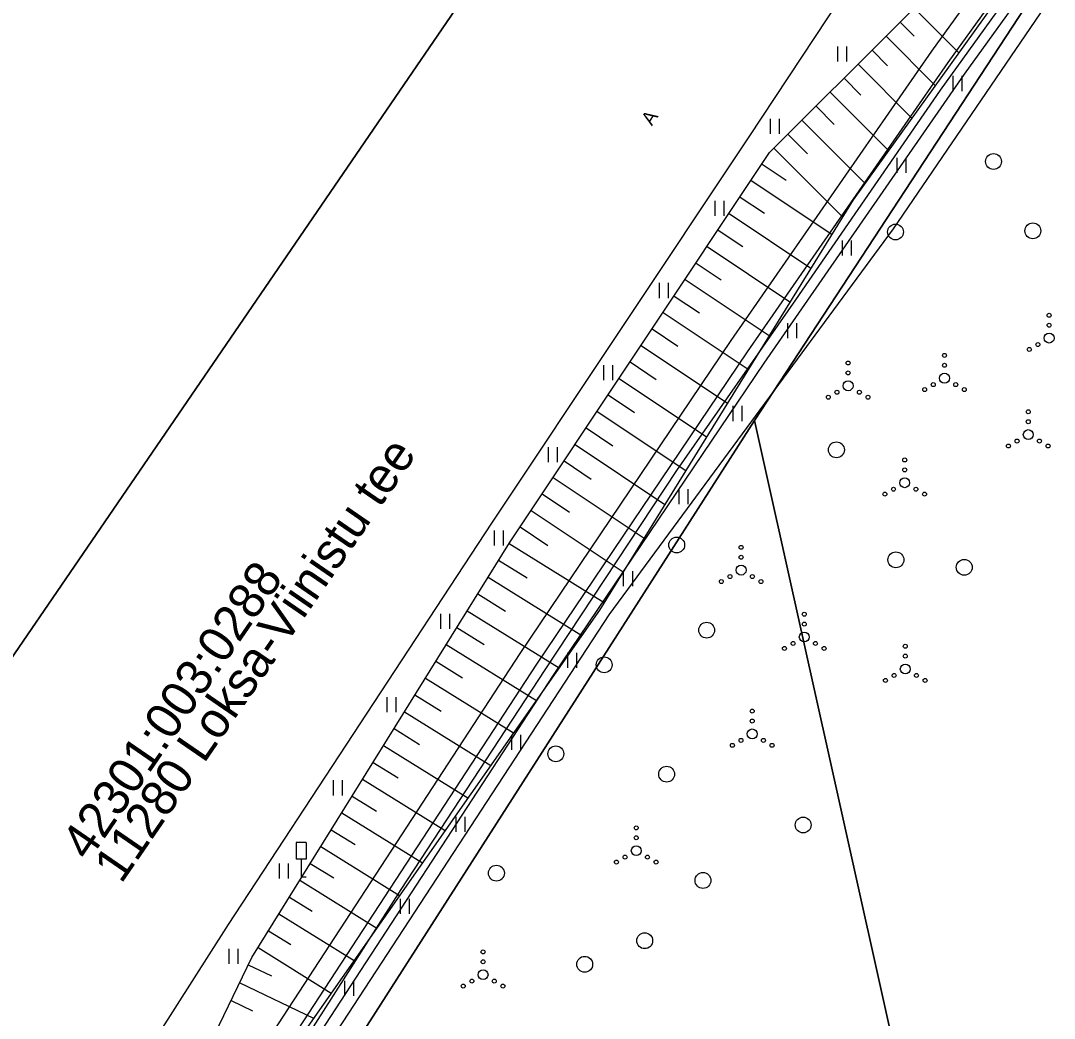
# Model space of a CAD drawing. Extents: x 599446 to 599962, y 6608194 to 6608886.
# Drawn here: x 599780.3 to 599832.4, y 6608609.2 to 6608659.5 of the extents above; entities that cross this region are included whole.
import ezdxf

# ---------------------------------------------------------------- set-up
doc = ezdxf.new("R2010")
doc.units = 0
for name, color, linetype in [('HALJASTUS', 7, 'Continuous'), ('KASUTUSALA', 7, 'Continuous'), ('LIIKLUS', 7, 'Continuous'), ('MPKAABEL', 7, 'Continuous'), ('PIIR', 7, 'Continuous'), ('PR_SIDE', 7, 'Continuous'), ('RELJEEF', 7, 'Continuous'), ('TEE', 7, 'Continuous')]:
    doc.layers.add(name, color=color, linetype=linetype)

msp = doc.modelspace()

# ---------------------------------------------------------------- linework, layer by layer
at = {"layer": 'HALJASTUS'}
for p, q in [((599821.508, 6608658.179), (599821.508, 6608657.418)), ((599821.963, 6608658.179), (599821.963, 6608657.418)), ((599827.314, 6608656.694), (599827.314, 6608655.933)), ((599827.769, 6608656.694), (599827.769, 6608655.933)), ((599818.112, 6608654.531), (599818.112, 6608653.77)), ((599818.567, 6608654.531), (599818.567, 6608653.77)), ((599824.489, 6608652.57), (599824.489, 6608651.808)), ((599824.944, 6608652.57), (599824.944, 6608651.808)), ((599815.31, 6608650.39), (599815.31, 6608649.629)), ((599815.765, 6608650.39), (599815.765, 6608649.629)), ((599821.732, 6608648.398), (599821.732, 6608647.637)), ((599822.187, 6608648.398), (599822.187, 6608647.637)), ((599812.509, 6608646.248), (599812.509, 6608645.487)), ((599812.964, 6608646.248), (599812.964, 6608645.487)), ((599818.975, 6608644.227), (599818.975, 6608643.466)), ((599819.43, 6608644.227), (599819.43, 6608643.466)), ((599809.707, 6608642.107), (599809.707, 6608641.346)), ((599810.162, 6608642.107), (599810.162, 6608641.346)), ((599816.231, 6608640.047), (599816.231, 6608639.286)), ((599816.686, 6608640.047), (599816.686, 6608639.286)), ((599806.906, 6608637.965), (599806.906, 6608637.204)), ((599807.361, 6608637.965), (599807.361, 6608637.204)), ((599813.506, 6608635.855), (599813.506, 6608635.094)), ((599813.962, 6608635.855), (599813.962, 6608635.094)), ((599804.193, 6608633.765), (599804.193, 6608633.004)), ((599804.648, 6608633.765), (599804.648, 6608633.004)), ((599810.701, 6608631.717), (599810.701, 6608630.956)), ((599811.156, 6608631.717), (599811.156, 6608630.956)), ((599801.482, 6608629.564), (599801.482, 6608628.803)), ((599801.937, 6608629.564), (599801.937, 6608628.803)), ((599807.88, 6608627.588), (599807.88, 6608626.827)), ((599808.336, 6608627.588), (599808.336, 6608626.827)), ((599798.771, 6608625.363), (599798.771, 6608624.602)), ((599799.226, 6608625.363), (599799.226, 6608624.602)), ((599805.064, 6608623.457), (599805.064, 6608622.696)), ((599805.519, 6608623.457), (599805.519, 6608622.696)), ((599796.06, 6608621.161), (599796.06, 6608620.4)), ((599796.515, 6608621.161), (599796.515, 6608620.4)), ((599802.254, 6608619.321), (599802.254, 6608618.56)), ((599802.709, 6608619.321), (599802.709, 6608618.56)), ((599793.349, 6608616.96), (599793.349, 6608616.199)), ((599793.804, 6608616.96), (599793.804, 6608616.199)), ((599799.444, 6608615.185), (599799.444, 6608614.424)), ((599799.899, 6608615.185), (599799.899, 6608614.424)), ((599790.805, 6608612.661), (599790.805, 6608611.899)), ((599791.26, 6608612.661), (599791.26, 6608611.899)), ((599796.634, 6608611.049), (599796.634, 6608610.288)), ((599797.089, 6608611.049), (599797.089, 6608610.288))]:
    msp.add_line(p, q, dxfattribs=at)
msp.add_lwpolyline([(599854.437, 6608582.858), (599845.632, 6608584.378), (599826.804, 6608588.268), (599809.044, 6608591.586), (599807.451, 6608590.502), (599796.451, 6608594.999), (599793.207, 6608594.269), (599791.661, 6608599.006), (599795.433, 6608607.227), (599809.992, 6608629.503), (599824.333, 6608648.974), (599834.941, 6608664.558), (599840.035, 6608665.745), (599843.227, 6608674.906), (599844.956, 6608681.949), (599852.543, 6608691.108)], dxfattribs=at)
for centre, radius in [((599829.374, 6608652.379), 0.4), ((599824.427, 6608648.821), 0.4), ((599831.357, 6608648.88), 0.4), ((599832.177, 6608644.619), 0.1), ((599832.177, 6608644.119), 0.1), ((599832.177, 6608643.469), 0.25), ((599831.612, 6608643.144), 0.1), ((599826.9, 6608642.596), 0.1), ((599831.177, 6608642.894), 0.1), ((599822.041, 6608642.212), 0.1), ((599826.9, 6608642.096), 0.1), ((599822.041, 6608641.712), 0.1), ((599826.9, 6608641.446), 0.25), ((599822.041, 6608641.062), 0.25), ((599825.9, 6608640.871), 0.1), ((599826.335, 6608641.121), 0.1), ((599827.465, 6608641.121), 0.1), ((599827.9, 6608640.871), 0.1), ((599821.041, 6608640.487), 0.1), ((599821.476, 6608640.737), 0.1), ((599822.606, 6608640.737), 0.1), ((599823.041, 6608640.487), 0.1), ((599831.125, 6608639.75), 0.1), ((599831.125, 6608639.25), 0.1), ((599830.56, 6608638.275), 0.1), ((599831.125, 6608638.6), 0.25), ((599831.69, 6608638.275), 0.1), ((599821.449, 6608637.832), 0.4), ((599830.125, 6608638.025), 0.1), ((599832.125, 6608638.025), 0.1), ((599824.893, 6608637.321), 0.1), ((599824.893, 6608636.821), 0.1), ((599824.893, 6608636.171), 0.25), ((599824.328, 6608635.846), 0.1), ((599825.458, 6608635.846), 0.1), ((599823.893, 6608635.596), 0.1), ((599825.893, 6608635.596), 0.1), ((599813.394, 6608633.032), 0.4), ((599816.644, 6608632.914), 0.1), ((599824.449, 6608632.286), 0.4), ((599816.644, 6608632.414), 0.1), ((599827.896, 6608631.905), 0.4), ((599816.644, 6608631.764), 0.25), ((599815.644, 6608631.189), 0.1), ((599816.079, 6608631.439), 0.1), ((599817.209, 6608631.439), 0.1), ((599817.644, 6608631.189), 0.1), ((599819.828, 6608629.539), 0.1), ((599814.905, 6608628.732), 0.4), ((599819.828, 6608629.039), 0.1), ((599819.828, 6608628.389), 0.25), ((599819.263, 6608628.064), 0.1), ((599820.393, 6608628.064), 0.1), ((599824.922, 6608627.924), 0.1), ((599818.828, 6608627.814), 0.1), ((599820.828, 6608627.814), 0.1), ((599824.922, 6608627.424), 0.1), ((599809.736, 6608626.986), 0.4), ((599824.922, 6608626.774), 0.25), ((599824.357, 6608626.449), 0.1), ((599825.487, 6608626.449), 0.1), ((599823.922, 6608626.199), 0.1), ((599825.922, 6608626.199), 0.1), ((599817.202, 6608624.65), 0.1), ((599817.202, 6608624.15), 0.1), ((599816.637, 6608623.175), 0.1), ((599817.202, 6608623.5), 0.25), ((599817.767, 6608623.175), 0.1), ((599807.297, 6608622.498), 0.4), ((599816.202, 6608622.925), 0.1), ((599818.202, 6608622.925), 0.1), ((599812.886, 6608621.469), 0.4), ((599819.771, 6608618.907), 0.4), ((599811.354, 6608618.76), 0.1), ((599811.354, 6608618.26), 0.1), ((599811.354, 6608617.61), 0.25), ((599810.354, 6608617.035), 0.1), ((599810.789, 6608617.285), 0.1), ((599811.919, 6608617.285), 0.1), ((599812.354, 6608617.035), 0.1), ((599804.301, 6608616.479), 0.4), ((599814.718, 6608616.11), 0.4), ((599811.781, 6608613.068), 0.4), ((599803.628, 6608612.504), 0.1), ((599803.628, 6608612.004), 0.1), ((599808.755, 6608611.88), 0.4), ((599803.628, 6608611.354), 0.25), ((599802.628, 6608610.779), 0.1), ((599803.063, 6608611.029), 0.1), ((599804.193, 6608611.029), 0.1), ((599804.628, 6608610.779), 0.1)]:
    msp.add_circle(centre, radius, dxfattribs=at)
at = {"layer": 'KASUTUSALA'}
for points in [[(599664.597, 6608420.143), (599679.582, 6608441.055), (599695.184, 6608463.081), (599714.018, 6608490.656), (599723.555, 6608504.017), (599729.674, 6608515.64), (599742.566, 6608533.808), (599749.114, 6608542.059), (599759.78, 6608557.976), (599766.815, 6608568.228), (599773.982, 6608577.739), (599779.71, 6608585.875), (599791.27, 6608602.691), (599792.262, 6608607.276), (599805.502, 6608627.565), (599816.139, 6608643.341), (599826.263, 6608657.946), (599831.93, 6608665.812)], [(599833.564, 6608664.658), (599827.897, 6608656.791), (599817.79, 6608642.212), (599807.169, 6608626.459), (599794.138, 6608606.492), (599793.141, 6608601.883), (599784.347, 6608589.09), (599785.079, 6608589.356), (599783.134, 6608586.523), (599783.007, 6608586.477), (599781.305, 6608584.666), (599775.607, 6608576.572), (599768.438, 6608567.06), (599761.435, 6608556.854), (599750.73, 6608540.879), (599744.166, 6608532.607), (599731.382, 6608514.591), (599725.261, 6608502.966), (599715.658, 6608489.511), (599696.826, 6608461.938), (599681.211, 6608439.895), (599666.292, 6608419.074)]]:
    msp.add_lwpolyline(points, dxfattribs=at)
at = {"layer": 'LIIKLUS'}
for p, q in [((599794.201, 6608618.025), (599794.201, 6608617.175)), ((599794.701, 6608618.025), (599794.201, 6608618.025)), ((599794.701, 6608618.025), (599794.701, 6608617.175)), ((599794.701, 6608617.175), (599794.201, 6608617.175)), ((599794.451, 6608617.175), (599794.451, 6608616.275)), ((599794.701, 6608616.275), (599794.451, 6608616.275))]:
    msp.add_line(p, q, dxfattribs=at)
at = {"layer": 'MPKAABEL'}
msp.add_lwpolyline([(599782.282, 6608586.259), (599782.254, 6608587.071), (599783.696, 6608589.145), (599783.897, 6608589.665), (599788.72, 6608596.889), (599790.415, 6608599.318), (599790.8, 6608600.309), (599791.153, 6608602.982), (599794.186, 6608607.324), (599799.494, 6608615.645), (599806.754, 6608626.738), (599813.397, 6608636.794), (599819.404, 6608645.396), (599826.694, 6608655.977), (599833.156, 6608664.947), (599839.759, 6608674.493), (599846.628, 6608685.702), (599850.041, 6608691.108)], dxfattribs=at)
at = {"layer": 'PIIR'}
for points in [[(599730.687, 6608555.172), (599752.04, 6608586.7), (599810.31, 6608671.87), (599822.957, 6608691.108)], [(599806.088, 6608691.108), (599810.31, 6608671.87), (599752.04, 6608586.7), (599735.826, 6608691.108)], [(599851.222, 6608691.108), (599817.31, 6608639.31), (599788.83, 6608594.82), (599746.81, 6608533.608)], [(599854.437, 6608583.323), (599828.73, 6608587.98), (599817.31, 6608639.31), (599851.222, 6608691.108)]]:
    msp.add_lwpolyline(points, dxfattribs=at)
msp.add_lwpolyline([(599817.31, 6608639.31), (599828.73, 6608587.98), (599788.83, 6608594.82)], close=True, dxfattribs=at)
at = {"layer": 'PR_SIDE'}
msp.add_lwpolyline([(599780.528, 6608585.299), (599792.205, 6608602.287), (599793.2, 6608606.884), (599806.336, 6608627.013), (599816.965, 6608642.777), (599827.08, 6608657.369), (599832.748, 6608665.235), (599837.963, 6608672.776), (599843.959, 6608682.55), (599849.32, 6608690.883), (599859.613, 6608707.157), (599866.762, 6608718.139), (599874.329, 6608729.392), (599883.015, 6608743.032), (599889.118, 6608752.665), (599898.415, 6608766.158), (599909.797, 6608783.03), (599920.302, 6608799.204), (599927.105, 6608809.792), (599929.059, 6608812.663), (599931.154, 6608813.844)], dxfattribs=at)
at = {"layer": 'RELJEEF'}
for p, q in [((599825.371, 6608660.111), (599827.618, 6608657.862)), ((599824.664, 6608659.404), (599825.373, 6608658.695)), ((599823.956, 6608658.697), (599826.435, 6608656.217)), ((599823.249, 6608657.99), (599824.027, 6608657.211)), ((599822.542, 6608657.283), (599825.251, 6608654.571)), ((599821.834, 6608656.576), (599822.682, 6608655.728)), ((599821.127, 6608655.87), (599824.068, 6608652.926)), ((599820.42, 6608655.163), (599821.337, 6608654.245)), ((599819.712, 6608654.456), (599822.885, 6608651.281)), ((599819.005, 6608653.749), (599819.991, 6608652.762)), ((599818.297, 6608653.042), (599821.753, 6608649.584)), ((599817.696, 6608652.248), (599818.908, 6608651.441)), ((599817.142, 6608651.416), (599821.21, 6608648.704)), ((599816.587, 6608650.584), (599817.816, 6608649.765)), ((599816.032, 6608649.752), (599820.159, 6608647.001)), ((599815.478, 6608648.92), (599816.724, 6608648.089)), ((599814.923, 6608648.088), (599819.107, 6608645.299)), ((599814.368, 6608647.256), (599815.632, 6608646.413)), ((599813.814, 6608646.424), (599818.056, 6608643.596)), ((599813.259, 6608645.592), (599814.54, 6608644.737)), ((599812.704, 6608644.76), (599817.005, 6608641.893)), ((599812.15, 6608643.928), (599813.449, 6608643.062)), ((599811.595, 6608643.095), (599815.954, 6608640.19)), ((599811.04, 6608642.263), (599812.357, 6608641.386)), ((599810.486, 6608641.431), (599814.902, 6608638.487)), ((599809.931, 6608640.599), (599811.265, 6608639.71)), ((599809.376, 6608639.767), (599813.851, 6608636.784)), ((599808.822, 6608638.935), (599810.173, 6608638.034)), ((599808.267, 6608638.103), (599812.8, 6608635.081)), ((599807.712, 6608637.271), (599809.081, 6608636.359)), ((599807.158, 6608636.439), (599811.749, 6608633.379)), ((599806.603, 6608635.607), (599807.989, 6608634.683)), ((599806.048, 6608634.775), (599810.697, 6608631.676)), ((599805.494, 6608633.943), (599806.897, 6608633.007)), ((599804.94, 6608633.11), (599809.742, 6608630.128)), ((599804.412, 6608632.26), (599805.845, 6608631.37)), ((599803.885, 6608631.411), (599808.614, 6608628.473)), ((599803.357, 6608630.562), (599804.762, 6608629.689)), ((599802.83, 6608629.712), (599807.465, 6608626.833)), ((599802.302, 6608628.863), (599803.678, 6608628.008)), ((599801.774, 6608628.013), (599806.315, 6608625.193)), ((599801.247, 6608627.164), (599802.595, 6608626.326)), ((599800.719, 6608626.314), (599805.166, 6608623.552)), ((599800.191, 6608625.465), (599801.511, 6608624.645)), ((599799.664, 6608624.615), (599804.016, 6608621.912)), ((599799.136, 6608623.766), (599800.428, 6608622.963)), ((599798.609, 6608622.916), (599802.867, 6608620.271)), ((599798.081, 6608622.067), (599799.344, 6608621.282)), ((599797.553, 6608621.217), (599801.717, 6608618.631)), ((599797.026, 6608620.368), (599798.261, 6608619.601)), ((599796.498, 6608619.518), (599800.568, 6608616.99)), ((599795.97, 6608618.669), (599797.177, 6608617.919)), ((599795.443, 6608617.819), (599799.418, 6608615.35)), ((599794.915, 6608616.97), (599796.094, 6608616.238)), ((599794.387, 6608616.12), (599798.269, 6608613.71)), ((599793.86, 6608615.271), (599795.01, 6608614.556)), ((599793.332, 6608614.421), (599797.119, 6608612.069)), ((599792.805, 6608613.572), (599793.927, 6608612.875)), ((599792.277, 6608612.723), (599795.97, 6608610.429)), ((599791.787, 6608611.852), (599792.949, 6608611.293)), ((599791.353, 6608610.951), (599795.079, 6608609.157)), ((599790.919, 6608610.05), (599791.993, 6608609.533))]:
    msp.add_line(p, q, dxfattribs=at)
for points in [[(599801.926, 6608592.213), (599793.207, 6608594.269), (599789.122, 6608596.036), (599787.113, 6608597.941), (599787.676, 6608601.107), (599788.191, 6608604.386), (599791.963, 6608612.218), (599804.959, 6608633.141), (599818.082, 6608652.827), (599831.188, 6608665.923), (599841.493, 6608683.919), (599846.39, 6608691.108)], [(599850.124, 6608691.108), (599843.352, 6608682.219), (599833.329, 6608665.805), (599822.288, 6608650.45), (599809.505, 6608629.745), (599794.311, 6608608.062), (599789.813, 6608601.009), (599790.211, 6608598.052), (599793.476, 6608595.009), (599801.926, 6608592.213)]]:
    msp.add_lwpolyline(points, dxfattribs=at)
at = {"layer": 'TEE'}
msp.add_lwpolyline([(599854.437, 6608581.395), (599845.399, 6608583.02), (599826.526, 6608586.694), (599801.842, 6608591.113), (599789.613, 6608594.125), (599786.413, 6608596.947), (599784.756, 6608598.98), (599784.301, 6608601.825), (599784.669, 6608604.283), (599790.786, 6608613.879), (599804.071, 6608634.135), (599817.047, 6608653.619), (599838.859, 6608686.624), (599841.837, 6608691.108)], dxfattribs=at)

# ---------------------------------------------------------------- texts
at = {"layer": 'PIIR'}
for s, p in [('11280 Loksa-Viinistu tee', (599785.377, 6608615.899)), ('42301:003:0288', (599783.729, 6608617.033))]:
    msp.add_text(s, height=1.8, rotation=55.4866, dxfattribs=at).set_placement(p)
at = {"layer": 'TEE'}
msp.add_text('A', height=0.7, rotation=56.7923, dxfattribs=at).set_placement((599812.142, 6608654.143))

doc.saveas('drawing.dxf')
